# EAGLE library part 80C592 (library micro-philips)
8051 -compatible 8bit Microcontroller CAN 2.0A
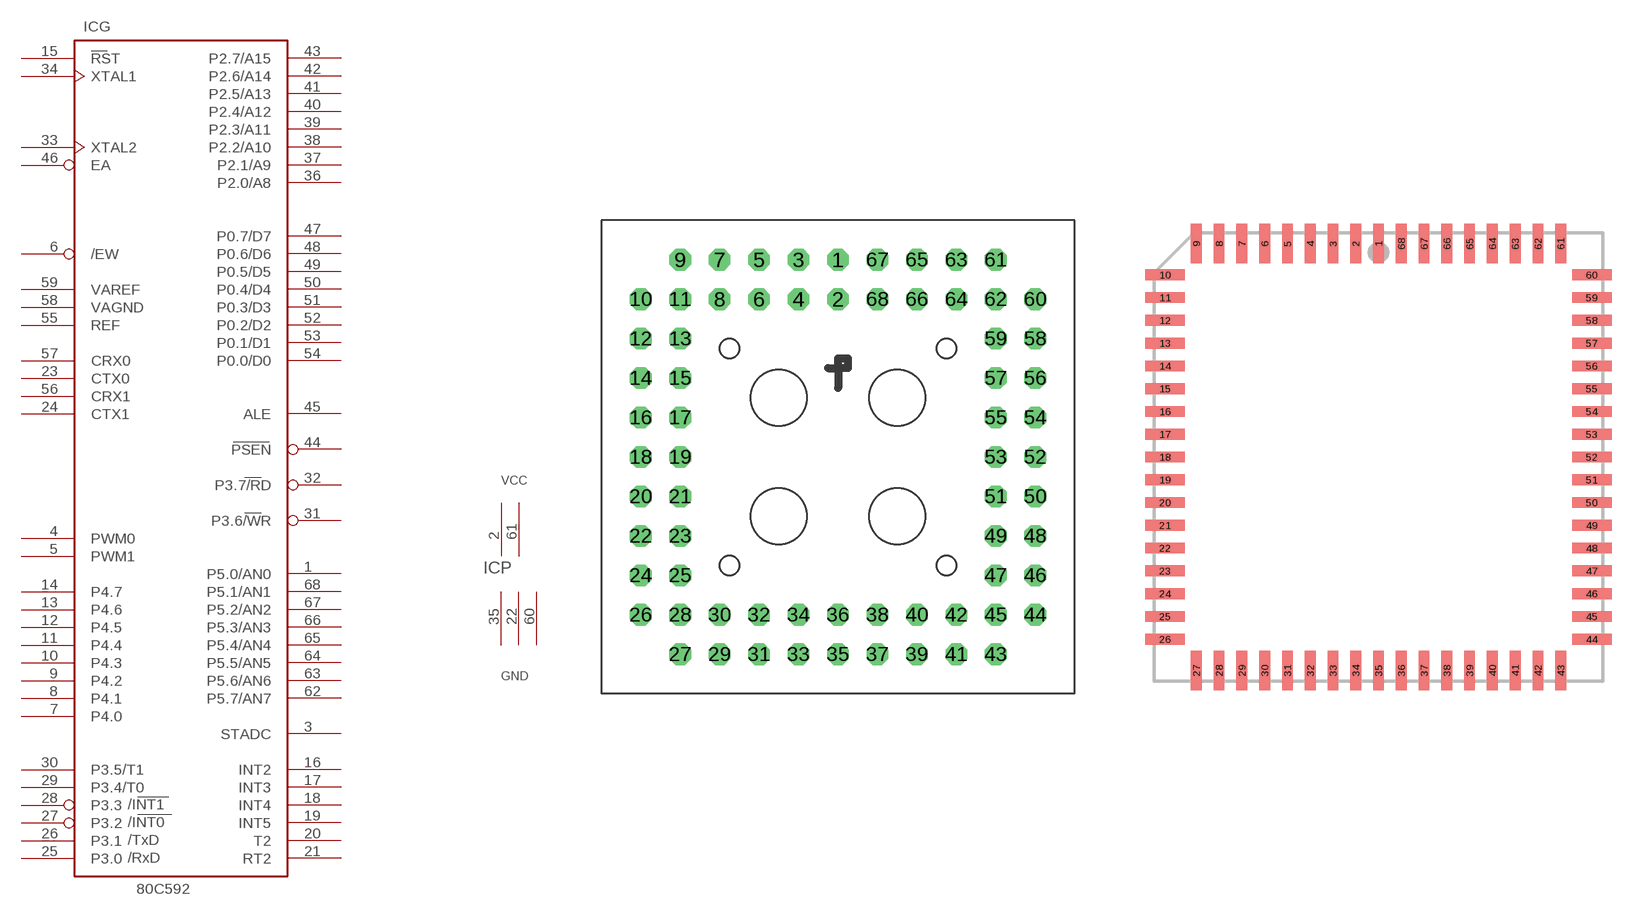
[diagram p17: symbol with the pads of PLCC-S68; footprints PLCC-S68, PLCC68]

Designator prefix IC; gates G=8XC592 P=PWR

## 80C592SOCKEL (OC_FARNELL: unknown; OC_NEWARK: unknown)  [PLCC-S68]
1  G:P5.0/AN0
2  P:VCC  pwr
3  G:STADC
4  G:PWM0
5  G:PWM1
6  G:/EW
7  G:P4.0
8  G:P4.1
9  G:P4.2
10  G:P4.3
11  G:P4.4
12  G:P4.5
13  G:P4.6
14  G:P4.7
15  G:RST  in
16  G:INT2
17  G:INT3
18  G:INT4
19  G:INT5
20  G:T2
21  G:RT2
22  P:CGND  pwr
23  G:CTX0
24  G:CTX1
25  G:P3.0
26  G:P3.1
27  G:P3.2
28  G:P3.3
29  G:P3.4/T0
30  G:P3.5/T1
31  G:P3.6/WR
32  G:P3.7/RD
33  G:XTAL2  in
34  G:XTAL1  in
35  P:GND  pwr
36  G:P2.0/A8
37  G:P2.1/A9
38  G:P2.2/A10
39  G:P2.3/A11
40  G:P2.4/A12
41  G:P2.5/A13
42  G:P2.6/A14
43  G:P2.7/A15
44  G:PSEN  out
45  G:ALE  out
46  G:EA  in
47  G:P0.7/D7
48  G:P0.6/D6
49  G:P0.5/D5
50  G:P0.4/D4
51  G:P0.3/D3
52  G:P0.2/D2
53  G:P0.1/D1
54  G:P0.0/D0
55  G:REF
56  G:CRX1
57  G:CRX0
58  G:VAGND
59  G:VAREF
60  P:AGND  pwr
61  P:AVCC  pwr
62  G:P5.7/AN7
63  G:P5.6/AN6
64  G:P5.5/AN5
65  G:P5.4/AN4
66  G:P5.3/AN3
67  G:P5.2/AN2
68  G:P5.1/AN1

## 80C592SMD (MPN: P80C592FFA/00,512; OC_FARNELL: 1085276; OC_NEWARK: 70R8453)  [PLCC68]
Pads as for PLCC-S68

## Footprint PLCC-S68 (pad centres in mm)
PLASTIC LEADED CHIP CARRIER Socked
drill 0.813 pad 1.397 octagon: 1 0,12.7; 2 0,10.16; 3 -2.54,12.7; 4 -2.54,10.16; 5 -5.08,12.7; 6 -5.08,10.16; 7 -7.62,12.7; 8 -7.62,10.16; 9 -10.16,12.7; 10 -12.7,10.16; 11 -10.16,10.16; 12 -12.7,7.62; 13 -10.16,7.62; 14 -12.7,5.08; 15 -10.16,5.08; 16 -12.7,2.54; 17 -10.16,2.54; 18 -12.7,0; 19 -10.16,0; 20 -12.7,-2.54; 21 -10.16,-2.54; 22 -12.7,-5.08; 23 -10.16,-5.08; 24 -12.7,-7.62; 25 -10.16,-7.62; 26 -12.7,-10.16; 27 -10.16,-12.7; 28 -10.16,-10.16; 29 -7.62,-12.7; 30 -7.62,-10.16; 31 -5.08,-12.7; 32 -5.08,-10.16; 33 -2.54,-12.7; 34 -2.54,-10.16; 35 0,-12.7; 36 0,-10.16; 37 2.54,-12.7; 38 2.54,-10.16; 39 5.08,-12.7; 40 5.08,-10.16; 41 7.62,-12.7; 42 7.62,-10.16; 43 10.16,-12.7; 44 12.7,-10.16; 45 10.16,-10.16; 46 12.7,-7.62; 47 10.16,-7.62; 48 12.7,-5.08; 49 10.16,-5.08; 50 12.7,-2.54; 51 10.16,-2.54; 52 12.7,0; 53 10.16,0; 54 12.7,2.54; 55 10.16,2.54; 56 12.7,5.08; 57 10.16,5.08; 58 12.7,7.62; 59 10.16,7.62; 60 12.7,10.16; 61 10.16,12.7; 62 10.16,10.16; 63 7.62,12.7; 64 7.62,10.16; 65 5.08,12.7; 66 5.08,10.16; 67 2.54,12.7; 68 2.54,10.16

## Footprint PLCC68 (pad centres in mm)
PLASTIC LEADED CHIP CARRIER square
smd 0.6 x 2.2: 1 0,11.9; 2 -1.27,11.9; 3 -2.54,11.9; 4 -3.81,11.9; 5 -5.08,11.9; 6 -6.35,11.9; 7 -7.62,11.9; 8 -8.89,11.9; 9 -10.16,11.9; 27 -10.16,-11.9; 28 -8.89,-11.9; 29 -7.62,-11.9; 30 -6.35,-11.9; 31 -5.08,-11.9; 32 -3.81,-11.9; 33 -2.54,-11.9; 34 -1.27,-11.9; 35 0,-11.9; 36 1.27,-11.9; 37 2.54,-11.9; 38 3.81,-11.9; 39 5.08,-11.9; 40 6.35,-11.9; 41 7.62,-11.9; 42 8.89,-11.9; 43 10.16,-11.9; 61 10.16,11.9; 62 8.89,11.9; 63 7.62,11.9; 64 6.35,11.9; 65 5.08,11.9; 66 3.81,11.9; 67 2.54,11.9; 68 1.27,11.9
smd 2.2 x 0.6: 10 -11.9,10.16; 11 -11.9,8.89; 12 -11.9,7.62; 13 -11.9,6.35; 14 -11.9,5.08; 15 -11.9,3.81; 16 -11.9,2.54; 17 -11.9,1.27; 18 -11.9,0; 19 -11.9,-1.27; 20 -11.9,-2.54; 21 -11.9,-3.81; 22 -11.9,-5.08; 23 -11.9,-6.35; 24 -11.9,-7.62; 25 -11.9,-8.89; 26 -11.9,-10.16; 44 11.9,-10.16; 45 11.9,-8.89; 46 11.9,-7.62; 47 11.9,-6.35; 48 11.9,-5.08; 49 11.9,-3.81; 50 11.9,-2.54; 51 11.9,-1.27; 52 11.9,0; 53 11.9,1.27; 54 11.9,2.54; 55 11.9,3.81; 56 11.9,5.08; 57 11.9,6.35; 58 11.9,7.62; 59 11.9,8.89; 60 11.9,10.16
